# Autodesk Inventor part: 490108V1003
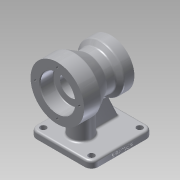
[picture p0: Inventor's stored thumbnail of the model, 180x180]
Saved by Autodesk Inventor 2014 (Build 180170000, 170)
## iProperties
Created: 2019-01
Part Number: 490108V1003
Material: 알루미늄 6061
Document SubType Name: Modeling
Designer: 601-05
Density: 2.71 g/cm^3
Appearance: 알루미늄 - 평지
Mass: 902.144 g
Surface Area: 600.964 cm^2
Volume: 332.895 cm^3
Author: 601-05
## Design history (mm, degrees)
sketch "스케치1"
  geometry: L1 (0, 0)-(0, 40); L2 (0, 40)-(25, 40); L3 (25, 40)-(45.785, 28); L4 (45.785, 28)-(59.126, 28); L5 (59.126, 28)-(65, 35); L6 (65, 35)-(80, 35); L7 (80, 35)-(80, 0); L8 (80, 0)-(0, 0)
  constraints: 16 end point, 4 parallel, 1 perpendicular, 1 vertical
  dimensions: "d9" = 30 deg angle of L4 L3; "d10" = 50 deg angle of L4 L5; "d11" = 80 diameter of L2 L8; "d12" = 70 diameter of L6 L8; "d13" = 25 distance of L1.end L2.end; "d14" = 15 distance of L5.end L6.end; "d16" = 56 diameter of L4 L8; "d17" = 80 distance of L7.end L1.start
revolve "회전1" sketch "스케치1" stored, may be unused: angle "d18" = 90 deg
sketch "스케치2"
  geometry: L1 (0, 0)-(0, 26); L2 (0, 26)-(19, 26); L3 (20, 25)-(20, 16); L4 (20, 16)-(63, 16); L5 (63, 16)-(63, 19.4); L6 (63.6, 20)-(80, 20); L7 (80, 20)-(80, 0); L8 (80, 0)-(0, 0); L9 (0, -40)-(0, 40) reference; L10 (80, -35)-(80, 35) reference; A1 r 1 centre (19, 25) between (20, 25) and (19, 26); A2 r 0.6 centre (63.6, 19.4) between (63.6, 20) and (63, 19.4)
  constraints: 16 end point, 6 parallel, 4 point on circle, 4 tangent, 2 centre point, 1 midpoint, 1 perpendicular, 1 vertical
  dimensions: "d19" = 20 distance between parallel lines of L3 L1; "d20" = 17 distance between parallel lines of L7 L5; "d21" = 52 diameter of L2 L8; "d22" = 32 diameter of L4 L8; "d23" = 40 diameter of L6 L8; "d24" = 1 radius of A1; "d25" = 0.6 radius of A2
revolve "회전2" sketch "스케치2" stored, may be unused: angle "d26" = 90 deg
node "작업 평면1"
node "작업축1"
  node "작업 평면2"
sketch "스케치3"
  geometry: L1 (0, 40)-(0, -40) reference; L2 (-5, 46)-(-97, 46); L3 (-97, 46)-(-97, -46); L4 (-97, -46)-(-5, -46); L5 (-5, -46)-(-5, 46); L6 (-5, 46)-(-97, -46); L7 (-97, 46)-(-5, -46); 3 further points
  constraints: 12 end point, 4 midpoint, 2 parallel, 1 horizontal, 1 horizontal alignment, 1 perpendicular
  dimensions: "d32" = 92 distance of L4.end L3.end; "d33" = 92 distance of L3.end L2.end; "d34" = 5 distance between parallel lines of L5 L1
extrude "돌출1" join sketch "스케치3" distance "d30" = 10; taper "d31" = 0 deg
sketch "스케치4"
  geometry: L1 (97, -46)-(97, 46) reference; L2 (97, 46)-(5, 46) reference; L3 (5, 46)-(5, -46) reference; L4 (50.199, 5)-(87, 5); L5 (87, 5)-(87, -5); L6 (87, -5)-(50.199, -5); L7 (51, -5)-(51, 5); L8 (97, -46)-(97, 46) reference; A1 r 16 centre (35, 0) between (51, 0) and (50.199, 5); 2 further points
  constraints: 8 end point, 3 point on circle, 2 horizontal alignment, 2 midpoint, 2 parallel, 2 point on line, 1 centre point, 1 horizontal, 1 perpendicular
  dimensions: "d36" = 16 radius of A1; "d37" = 10 distance between parallel lines of L6 L4; "d38" = 10 distance between parallel lines of L5 L1; "d39" = 46 distance from line of A1.centre L2 (derived); "d40" = 30 distance from line of A1.centre L3
extrude "돌출2" join sketch "스케치4" stored distance "d41" = 10; taper "d42" = 0 deg
extrude "돌출3" join sketch "스케치4" distance "d43" = 45; taper "d44" = 0 deg
feature "면 기울기1" dims angle "d45" = 25 deg
sketch "스케치5" dims "d46" = 66
  geometry: C1 r 26 at (0, 0) reference; C2 r 40 at (0, 0) reference; 2 further points
  constraints: 3 coincident, 2 vertical alignment, 2 other
hole "구멍1" sketch "스케치5" at (0, 33) diameter "d47" = 3.242; stored, may be unused: countersink angle "d51" = 90 deg, drill point angle "d53" = 118 deg; dims "d48" = 9, "d49" = 4, "d50" = 2, "d52" = 11
sketch "스케치6" dims "d57" = 55
  geometry: C1 r 20 at (0, 0) reference; C2 r 35 at (0, 0) reference; 2 further points
  constraints: 3 coincident, 2 vertical alignment, 2 other
hole "구멍2" sketch "스케치6" at (0, 27.5) diameter "d58" = 3.242; stored, may be unused: countersink angle "d62" = 90 deg, drill point angle "d64" = 118 deg; dims "d59" = 9, "d60" = 4, "d61" = 2, "d63" = 11
fillet "모깎기1" dims "d68" = 3
fillet "모깎기2" dims "d69" = 3
fillet "모깎기3" dims "d70" = 3
fillet "모깎기4" dims "d71" = 10
sketch "스케치7"
  geometry: C1 r 4.5 at (15, 36); C2 r 4.5 at (87, 36); C3 r 4.5 at (15, -36); C4 r 4.5 at (87, -36); A1 r 10 centre (15, 36) between (15, 46) and (5, 36) reference; A2 r 10 centre (15, -36) between (5, -36) and (15, -46) reference; A3 r 10 centre (87, -36) between (87, -46) and (97, -36) reference; A4 r 10 centre (87, 36) between (97, 36) and (87, 46) reference; 1 further point
  constraints: 4 centre point, 4 coincident
  dimensions: "d72" = 9 diameter of C1; "d73" = 9 diameter of C2; "d74" = 9 diameter of C3; "d75" = 9 diameter of C4
extrude "돌출4" cut sketch "스케치7" stored distance "d76" = 10; taper "d77" = 0 deg
chamfer "모따기1" distance "d78" = 1; stored, may be unused: second distance "d79" = 2, angle "d80" = 45 deg
chamfer "모따기2" distance "d81" = 1; stored, may be unused: second distance "d82" = 2, angle "d83" = 45 deg
fillet "모깎기5" dims "d84" = 3
sketch "스케치8"
  geometry: L1 (82, 0)-(72, 0) reference; L2 (-10, 7)-(-10, 0) reference; 2 further points
  constraints: 1 other
  dimensions: "d85" = 4 distance from line of point (36, 4) L1; "d86" = 46 distance from line of point (36, 4) L2
feature "엠보싱1" sketch "스케치8" dims "d19" = 20, "d20" = 17, "d21" = 52, "d22" = 32, "d23" = 40, "d24" = 1, "d25" = 0.6, "d87" = 0.5, "d88" = 0
node "솔리드1"
pattern_circular "원형 패턴1" dims angle "d55" = 360 deg
pattern_circular "원형 패턴2" dims angle "d66" = 360 deg
